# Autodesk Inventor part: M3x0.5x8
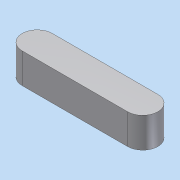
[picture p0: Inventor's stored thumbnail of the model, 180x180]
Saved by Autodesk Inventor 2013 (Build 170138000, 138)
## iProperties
Company: 한국ATC센터
Created: 2009-02
Part Number: M3x0.5x8
Document SubType Name: Modeling
Designer: KYOUNG IL JANG
Density: 1 g/cm^3
Mass: 0.274265 g
Surface Area: 2.99398 cm^2
Volume: 0.274265 cm^3
Vendor: CBT Solutions
Material: 일반
Author: KYOUNG IL JANG
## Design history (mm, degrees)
sketch "스케치1"
  geometry: L1 (0, 2)-(14, 2); L2 (0, -2)-(14, -2); A1 r 2 centre (0, 0) between (0, 2) and (0, -2); A2 r 2 centre (14, 0) between (14, -2) and (14, 2); 1 further point
  constraints: 4 end point, 4 point on circle, 3 tangent, 2 centre point, 1 coincident, 1 equal radius, 1 horizontal alignment, 1 parallel
  dimensions: "d0" = 4 distance between parallel lines of L2 L1; "d1" = 18 dimension on A2 A1
extrude "돌출1" new body sketch "스케치1" distance "d2" = 4; taper "d3" = 0 deg
node "솔리드1"
